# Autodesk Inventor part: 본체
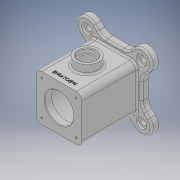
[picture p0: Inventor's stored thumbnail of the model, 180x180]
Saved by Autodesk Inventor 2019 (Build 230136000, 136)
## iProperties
Created: 2021-01
Part Number: 본체
Material: 일반
Document SubType Name: Modeling
Designer: 3DPRO17
Density: 1 g/cm^3
Appearance: 기본값
Mass: 385.865 g
Surface Area: 854.376 cm^2
Volume: 385.865 cm^3
Author: 3DPRO17
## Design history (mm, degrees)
sketch "스케치2"
  geometry: L1 (48, 48)-(-48, 48); L2 (-48, 48)-(-48, -48); L3 (-48, -48)-(48, -48); L4 (48, -48)-(48, 48); L5 (48, 48)-(-48, -48); L6 (-48, 48)-(48, -48); 1 further point
  constraints: 12 end point, 2 midpoint, 2 parallel, 1 horizontal, 1 perpendicular
  dimensions: "d16" = 96 distance of L3.end L2.end; "d17" = 96 distance of L2.end L1.end
extrude "돌출1" new body sketch "스케치2" distance "d18" = 12; taper "d19" = 0 deg
sketch "스케치3"
  geometry: L1 (-40, -40)-(40, -40); L2 (40, -40)-(40, 40); L3 (40, 40)-(-40, 40); L4 (-40, 40)-(-40, -40); L5 (-40, -40)-(40, 40); L6 (40, -40)-(-40, 40); 1 further point
  constraints: 12 end point, 2 midpoint, 2 parallel, 1 horizontal, 1 perpendicular
  dimensions: "d20" = 80 distance of L3.end L2.end; "d21" = 80 distance of L2.end L1.end
extrude "돌출2" join sketch "스케치3" distance "d22" = 96; taper "d23" = 0 deg
sketch "스케치4"
  geometry: L1 (-48, 48)-(48, 48) reference; L2 (-48, -48)-(-48, 48) reference; L3 (48, -48)-(-48, -48) reference; L4 (48, 48)-(48, -48) reference; L5 (-47.376, -47.376)-(0, 0); L6 (0, 0)-(47.376, -47.376); L7 (0, 0)-(-47.376, 47.376); L8 (0, 0)-(47.376, 47.376); C1 r 18 at (47.376, -47.376); C2 r 18 at (-47.376, -47.376); C3 r 18 at (47.376, 47.376); C4 r 18 at (-47.376, 47.376); A1 r 67 centre (0, 0) between (47.376, -47.376) and (-47.376, -47.376); 1 further point
  constraints: 8 end point, 5 centre point, 4 point on circle, 2 horizontal alignment, 1 coincident
  dimensions: "d24" = 134 diameter of A1; "d25" = 36 diameter of C1; "d26" = 36 diameter of C2; "d28" = 36 diameter of C3; "d29" = 36 diameter of C4; "d100" = 45 deg angle of L4 L8; "d101" = 45 deg angle of L5 L2
extrude "돌출3" join sketch "스케치4" distance "d31" = 12; taper "d32" = 0 deg
sketch "스케치5"
  geometry: C1 r 25 at (0, 0); 1 further point
  constraints: 1 centre point, 1 coincident
  dimensions: "d34" = 50 diameter of C1
extrude "돌출4" cut sketch "스케치5" stored distance "d35" = 50 (= d34); taper "d36" = 0 deg
node "작업 평면2"
sketch "스케치8"
  geometry: C1 r 35 at (0, 0); 1 further point
  constraints: 1 centre point, 1 coincident
  dimensions: "d42" = 70 diameter of C1
extrude "돌출6" cut sketch "스케치8" distance "d43" = 84; taper "d44" = 0 deg
sketch "스케치9"
  geometry: L1 (10.613, -12)-(69.387, -12) reference; C1 r 20 at (40, 47); 4 further points
  constraints: 1 centre point, 1 midpoint, 1 vertical alignment
  dimensions: "d45" = 40 diameter of C1; "d46" = 59 distance from line of C1.centre L1
extrude "돌출7" join sketch "스케치9" distance "d47" = 15; taper "d48" = 0 deg
sketch "스케치10"
  geometry: C1 r 20 at (0, 0) reference; 2 further points
  constraints: 1 coincident
hole "구멍1" sketch "스케치10" at (0, 0) diameter "d49" = 25; stored, may be unused: countersink angle "d53" = 90 deg, drill point angle "d55" = 0 deg; dims "d50" = 8, "d51" = 30, "d52" = 8, "d54" = 10
sketch "스케치12"
  geometry: C1 r 9 at (-47.376, 47.376); C2 r 5 at (-47.376, 47.376); A1 r 18 centre (-47.376, 47.376) between (-29.387, 48) and (-48, 29.387) reference; 3 further points
  constraints: 2 centre point, 2 concentric
  dimensions: "d62" = 18 diameter of C1; "d63" = 10 diameter of C2
extrude "돌출9" cut sketch "스케치12" stored distance "d64" = 15; taper "d65" = 0 deg
extrude "돌출10" cut sketch "스케치12" distance "d66" = 4; taper "d67" = 0 deg
sketch "스케치13"
  geometry: L1 (30, -30)-(-30, -30); L2 (-30, -30)-(-30, 30); L3 (-30, 30)-(30, 30); L4 (30, 30)-(30, -30); L5 (30, -30)-(-30, 30); L6 (-30, -30)-(30, 30); 5 further points
  constraints: 12 end point, 4 coincident, 2 midpoint, 2 parallel, 1 horizontal, 1 perpendicular
  dimensions: "d68" = 60 distance of L2.end L3.end; "d69" = 60 distance of L1.end L2.end
hole "구멍2" sketch "스케치13" at (-30, -30), (-30, 30), (30, 30), (30, -30) diameter "d70" = 3.242; stored, may be unused: countersink angle "d74" = 90 deg, drill point angle "d76" = 118 deg; dims "d71" = 8, "d72" = 30, "d73" = 8, "d75" = 10
sketch "스케치14"
  geometry: L1 (-30, 30)-(30, 30); L2 (30, 30)-(30, -30); L3 (30, -30)-(-30, -30); L4 (-30, -30)-(-30, 30); L5 (-30, 30)-(30, -30); L6 (30, 30)-(-30, -30); C1 r 1.621 at (30, -30) reference; 5 further points
  constraints: 12 end point, 4 coincident, 2 midpoint, 2 parallel, 1 horizontal, 1 perpendicular
  dimensions: "d77" = 60 distance of L2.end L3.end; "d78" = 60 distance of L1.end L2.end
hole "구멍3" sketch "스케치14" at (30, 30), (30, -30), (-30, -30), (-30, 30) diameter "d79" = 3.242; stored, may be unused: countersink angle "d83" = 90 deg, drill point angle "d85" = 118 deg; dims "d80" = 8, "d81" = 30, "d82" = 8, "d84" = 10
sketch "스케치15"
  geometry: L1 (0, 96)-(80, 96) reference; C1 r 20 at (40, 47) reference; 2 further points
  constraints: 1 vertical alignment, 1 other
  dimensions: "d86" = 10 distance from line of point (40, 86) L1
feature "엠보싱1" sketch "스케치15" dims "d16" = 96, "d17" = 96, "d28" = 36, "d87" = 0.5, "d88" = 0
fillet "모깎기2" dims "d89" = 10
chamfer "모따기1" distance "d90" = 1; stored, may be unused: second distance "d91" = 2, angle "d92" = 45 deg
fillet "모깎기5" dims "d95" = 3
chamfer "모따기2" distance "d96" = 1; stored, may be unused: second distance "d97" = 2, angle "d98" = 45 deg
sketch "스케치16"
  geometry: L1 (-48, 29.387)-(-48, -29.387) reference; L2 (0, 0)-(-47.376, 47.376); L3 (-48, 22.544)-(-60.104, 34.648); L4 (-22.544, 48)-(-34.648, 60.104); L5 (29.387, 48)-(-29.387, 48) reference; L6 (-48, 22.544)-(-48, 29.387); L7 (-29.387, 48)-(-22.544, 48); A1 r 18 centre (-47.376, 47.376) between (-29.387, 48) and (-48, 29.387) reference; A2 r 18 centre (-47.376, 47.376) between (-29.387, 48) and (-34.648, 60.104); A3 r 18 centre (-47.376, 47.376) between (-60.104, 34.648) and (-48, 29.387)
  constraints: 10 end point, 4 point on circle, 3 point on line, 2 centre point, 2 parallel, 2 tangent, 1 coincident, 1 collinear, 1 concentric, 1 perpendicular
extrude "돌출11" join sketch "스케치16" distance "d102" = 12; taper "d103" = 0 deg
fillet "모깎기6" dims "d107" = 20
fillet "모깎기7" dims "d108" = 3
node "솔리드1"
mirror "미러1"
mirror "미러2"
pattern_circular "원형 패턴1" dims angle "d105" = 360 deg
node "투영된 루프1"
other parameters: "d2" = 134, "d41" = 12
